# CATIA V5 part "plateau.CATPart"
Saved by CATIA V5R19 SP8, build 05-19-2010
Part number: plateau
Publications: "Diametre_exterieur"
Bounding box of the stored display mesh (mm): x 0 to 14, y -130 to 130, z -129.809 to 129.809
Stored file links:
  G:\EU_thinkMotion\CFAO_2010\SIL_groupe2\SIL_groupe2\msauret\Brevet_Sauret_parametre\plateau.CATPart
  F:\Brevet_Sauret paramétré\Product3.CATProduct
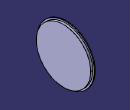
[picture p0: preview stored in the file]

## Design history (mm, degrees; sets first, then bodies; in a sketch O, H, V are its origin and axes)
Parameters
  Rayon_exterieur = 130 mm
Set1
  Plane1: linked copy from another document
Body1 (main body)
  Sketch1 on Plane1, origin (0, 0, 0), H (0, 1, 0), V (0, 0, 1)
    circle A1 centre (0, 0) radius 130
  Pad1: profile Sketch1, direction (1, 0, 0), length 4
  Sketch2 on end face of Pad1, origin (4, 0, 0), H (0, 1, 0), V (0, 0, 1)
    circle A1 centre (0, 0) radius 123
    radius A1 = 123 {= Rayon_exterieur -7mm}
  Pad2: profile Sketch2, direction (1, 0, 0), length 10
